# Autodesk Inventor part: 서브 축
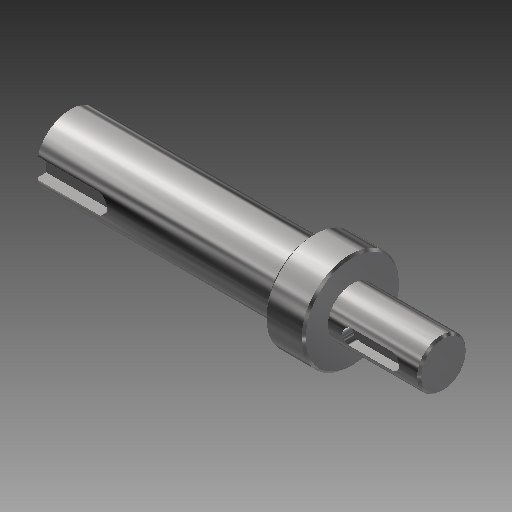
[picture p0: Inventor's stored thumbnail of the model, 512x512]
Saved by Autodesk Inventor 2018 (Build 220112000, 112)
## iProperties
Created: 2016-04
Part Number: 서브 축
Document SubType Name: Modeling
Designer: mdu
Density: 1 g/cm^3
Mass: 19.9624 g
Surface Area: 57.7178 cm^2
Volume: 19.9624 cm^3
Material: 강철, 연강
Appearance: 반광택
Author: mdu
Revision Number: 1
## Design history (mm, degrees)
sketch "스케치1"
  geometry: L1 (-16.331, 0)-(-108.831, 0); L2 (-16.331, 0)-(-16.331, -6); L3 (-16.331, -6)-(-38.831, -6); L4 (-38.831, -12)-(-46.5, -12); L5 (-46.5, -8.5)-(-108.831, -8.5); L6 (-108.831, -8.5)-(-108.831, 0); L7 (-46.5, -8.5)-(-46.5, -12); L8 (-38.831, -6)-(-38.831, -12); L9 (-46.5, 12.249)-(-46.5, -12.249) reference; L10 (-38.831, -17)-(-38.831, 17) reference; 2 further points
  constraints: 17 end point, 4 perpendicular, 2 collinear, 2 parallel, 1 horizontal, 1 midpoint, 1 point on line
  dimensions: "d1" = 12 diameter of L3 L1; "d2" = 24 diameter of L4 L1; "d3" = 17 diameter of L5 L1; "d18" = 22.5 distance of L2.end L3.end; "d20" = 70 distance between parallel lines of L6 L8; "d21" = 7.66872 distance of L4.start L4.end (derived)
revolve "회전1" sketch "스케치1" stored, may be unused: angle "d5" = 90 deg
feature "면 이동1"
chamfer "모따기1" distance "d6" = 0.5; stored, may be unused: second distance "d7" = 2, angle "d8" = 45 deg
node "작업 평면1"
sketch "스케치2"
  geometry: L1 (11.25, 5.5)-(11.25, -5.5) reference; L2 (-5.75, -2)-(4.25, -2); L3 (4.25, 2)-(-5.75, 2); A1 r 2 centre (4.25, 0) between (4.25, -2) and (4.25, 2); A2 r 2 centre (-5.75, 0) between (-5.75, 2) and (-5.75, -2); 2 further points
  constraints: 4 end point, 4 point on circle, 4 tangent, 2 centre point, 1 horizontal alignment, 1 midpoint, 1 parallel, 1 perpendicular
  dimensions: "d9" = 4 distance between parallel lines of L2 L3; "d10" = 14 dimension on A1 A2; "d11" = 5 distance edge to line of A1 L1
extrude "돌출1" cut sketch "스케치2" distance "d12" = 2.5; taper "d13" = 0 deg
node "작업 평면2"
sketch "스케치3"
  geometry: L1 (-31.166, -8)-(-31.166, 8) reference; L2 (-31.166, 2.5)-(-15.666, 2.5); L3 (-15.666, -2.5)-(-31.166, -2.5); A1 r 2.5 centre (-15.666, 0) between (-15.666, -2.5) and (-15.666, 2.5); 2 further points
  constraints: 4 end point, 2 perpendicular, 2 point on circle, 2 point on line, 2 tangent, 1 centre point, 1 horizontal alignment, 1 midpoint
  dimensions: "d14" = 5 distance between parallel lines of L3 L2; "d15" = 18 dimension on A1 L1
extrude "돌출2" cut sketch "스케치3" distance "d16" = 3; taper "d17" = 0 deg
node "솔리드1"
node "참조4"
node "참조5"
